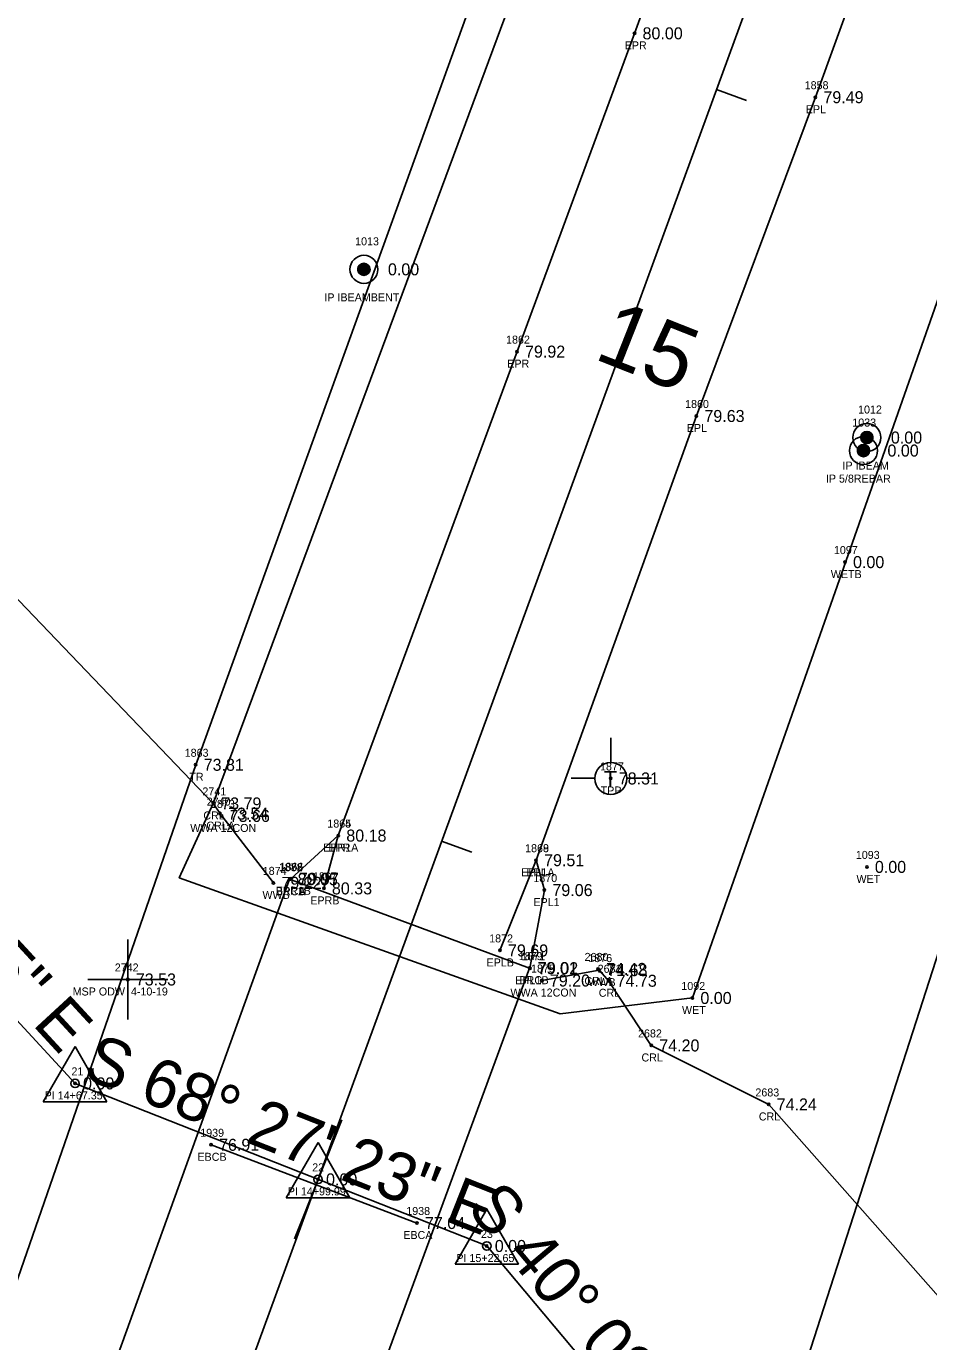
# Model space of a CAD drawing. Extents: x 2139392 to 2143384, y 505395 to 510520.
# Drawn here: x 2140668.2 to 2140780.9, y 508341.4 to 508505.7 of the extents above; entities that cross this region are included whole.
import ezdxf

# ---------------------------------------------------------------- set-up
doc = ezdxf.new("R2010")
doc.units = 0
for name, color, linetype in [('RD_EV_EX_Wetlands', 7, 'Continuous'), ('RD_EX_Bridge', 7, 'Continuous'), ('RD_EX_Bridge_txCode', 7, 'Continuous'), ('RD_EX_DV_Prop_txCode', 7, 'Continuous'), ('RD_EX_DV_PropPin', 7, 'Continuous'), ('RD_EX_H2O', 7, 'Continuous'), ('RD_EX_H2O_txCode', 7, 'Continuous'), ('RD_EX_H2O_WetLd_txCode', 7, 'Continuous'), ('RD_EX_Road', 7, 'Continuous'), ('RD_EX_Road_txCode', 7, 'Continuous'), ('RD_EX_TX_Bridge_ELEV', 7, 'Continuous'), ('RD_EX_TX_DV_Prop_ELEV', 7, 'Continuous'), ('RD_EX_TX_H2O_ELEV', 7, 'Continuous'), ('RD_EX_TX_H2O_WetLd_ELEV', 7, 'Continuous'), ('RD_EX_TX_Misc_ELEV', 7, 'Continuous'), ('RD_EX_TX_Road_ELEV', 7, 'Continuous'), ('RD_EX_TX_UT_ELEV', 7, 'Continuous'), ('RD_EX_TX_VEG_ELEV', 7, 'Continuous'), ('RD_EX_UT', 7, 'Continuous'), ('RD_EX_UT_txCode', 7, 'Continuous'), ('RD_EX_VEG', 7, 'Continuous'), ('RD_EX_VEG_txCode', 7, 'Continuous'), ('RD_HC_Cl', 7, 'Continuous'), ('RD_HC_Data', 7, 'Continuous'), ('RD_HC_Data_Tic', 7, 'Continuous'), ('RD_HC_Survey_ELEV', 7, 'Continuous'), ('RD_HC_TX_Sta50', 7, 'Continuous'), ('RD_HC_txCode', 7, 'Continuous'), ('RD_SMD_Locator', 7, 'Continuous')]:
    doc.layers.add(name, color=color, linetype=linetype)

msp = doc.modelspace()

# ---------------------------------------------------------------- linework, layer by layer
at = {"layer": 'RD_EV_EX_Wetlands'}
for p, q in [((2141031.31, 509324.16), (2140691.53, 508408.63)), ((2141075.3, 509306.14), (2140751.4, 508384.33)), ((2140734.86, 508382.37), (2140751.4, 508384.33))]:
    msp.add_line(p, q, dxfattribs=at)
msp.add_lwpolyline([(2140734.86, 508382.37), (2140687.28, 508399.34), (2140691.53, 508408.63)], dxfattribs=at)
at = {"layer": 'RD_EX_Bridge'}
for p, q in [((2140692.59, 508407.07), (2140699.06, 508398.71)), ((2140732.59, 508386.51), (2140739.77, 508387.81)), ((2140716.99, 508356.22), (2140691.26, 508365.99))]:
    msp.add_line(p, q, dxfattribs=at)
msp.add_lwpolyline([(2140701.08, 508399.16), (2140731.05, 508388.06), (2140707.41, 508323.76), (2140677.81, 508334.75), (2140701.08, 508399.16)], dxfattribs=at)
at = {"layer": 'RD_EX_DV_PropPin'}
for p, q in [((2140709.62, 508475.15), (2140709.62, 508475.54)), ((2140709.66, 508475.05), (2140709.66, 508475.64)), ((2140709.69, 508474.98), (2140709.69, 508475.71)), ((2140709.73, 508474.92), (2140709.73, 508475.77)), ((2140709.76, 508474.87), (2140709.76, 508475.82)), ((2140709.8, 508474.83), (2140709.8, 508475.86)), ((2140709.83, 508474.79), (2140709.83, 508475.9)), ((2140709.87, 508474.76), (2140709.87, 508475.93)), ((2140709.9, 508474.74), (2140709.9, 508475.95)), ((2140709.94, 508474.71), (2140709.94, 508475.98)), ((2140709.97, 508474.69), (2140709.97, 508476)), ((2140710.01, 508474.67), (2140710.01, 508476.02)), ((2140710.04, 508474.65), (2140710.04, 508476.04)), ((2140710.08, 508474.64), (2140710.08, 508476.05)), ((2140710.11, 508474.62), (2140710.11, 508476.07)), ((2140710.15, 508474.61), (2140710.15, 508476.08)), ((2140710.18, 508474.6), (2140710.18, 508476.09)), ((2140710.22, 508474.6), (2140710.22, 508476.09)), ((2140710.25, 508474.59), (2140710.25, 508476.1)), ((2140710.29, 508474.59), (2140710.29, 508476.1)), ((2140710.32, 508474.58), (2140710.32, 508476.11)), ((2140710.36, 508474.58), (2140710.36, 508476.11)), ((2140710.39, 508474.58), (2140710.39, 508476.11)), ((2140710.43, 508474.59), (2140710.43, 508476.1)), ((2140710.46, 508474.59), (2140710.46, 508476.1)), ((2140710.5, 508474.6), (2140710.5, 508476.09)), ((2140710.53, 508474.6), (2140710.53, 508476.09)), ((2140710.57, 508474.61), (2140710.57, 508476.08)), ((2140710.6, 508474.62), (2140710.6, 508476.07)), ((2140710.64, 508474.64), (2140710.64, 508476.05)), ((2140710.67, 508474.65), (2140710.67, 508476.04)), ((2140710.71, 508474.67), (2140710.71, 508476.02)), ((2140710.74, 508474.69), (2140710.74, 508476)), ((2140710.78, 508474.71), (2140710.78, 508475.98)), ((2140710.81, 508474.74), (2140710.81, 508475.95)), ((2140710.85, 508474.76), (2140710.85, 508475.93)), ((2140710.88, 508474.79), (2140710.88, 508475.9)), ((2140710.92, 508474.83), (2140710.92, 508475.86)), ((2140710.95, 508474.87), (2140710.95, 508475.82)), ((2140710.99, 508474.92), (2140710.99, 508475.77)), ((2140711.02, 508474.98), (2140711.02, 508475.71)), ((2140711.06, 508475.05), (2140711.06, 508475.64)), ((2140711.09, 508475.15), (2140711.09, 508475.54)), ((2140772.47, 508454.14), (2140772.47, 508454.53)), ((2140772.5, 508454.04), (2140772.5, 508454.64)), ((2140772.54, 508453.97), (2140772.54, 508454.71)), ((2140772.57, 508453.91), (2140772.57, 508454.76)), ((2140772.61, 508453.86), (2140772.61, 508454.81)), ((2140772.64, 508453.82), (2140772.64, 508454.85)), ((2140772.68, 508453.79), (2140772.68, 508454.89)), ((2140772.71, 508453.76), (2140772.71, 508454.92)), ((2140772.75, 508453.73), (2140772.75, 508454.95)), ((2140772.78, 508453.7), (2140772.78, 508454.97)), ((2140772.82, 508453.68), (2140772.82, 508454.99)), ((2140772.85, 508453.66), (2140772.85, 508455.01)), ((2140772.89, 508453.65), (2140772.89, 508455.03)), ((2140772.92, 508453.63), (2140772.92, 508455.05)), ((2140772.96, 508453.62), (2140772.96, 508455.06)), ((2140772.99, 508453.61), (2140772.99, 508455.07)), ((2140773.03, 508453.6), (2140773.03, 508455.08)), ((2140773.06, 508453.59), (2140773.06, 508455.09)), ((2140773.1, 508453.58), (2140773.1, 508455.09)), ((2140773.13, 508453.58), (2140773.13, 508455.1)), ((2140773.17, 508453.58), (2140773.17, 508455.1)), ((2140773.2, 508453.58), (2140773.2, 508455.1)), ((2140773.24, 508453.58), (2140773.24, 508455.1)), ((2140773.27, 508453.58), (2140773.27, 508455.1)), ((2140773.31, 508453.58), (2140773.31, 508455.09)), ((2140773.34, 508453.59), (2140773.34, 508455.09)), ((2140773.38, 508453.6), (2140773.38, 508455.08)), ((2140773.41, 508453.61), (2140773.41, 508455.07)), ((2140773.45, 508453.62), (2140773.45, 508455.06)), ((2140773.48, 508453.63), (2140773.48, 508455.05)), ((2140773.52, 508453.65), (2140773.52, 508455.03)), ((2140773.55, 508453.66), (2140773.55, 508455.01)), ((2140773.59, 508453.68), (2140773.59, 508454.99)), ((2140773.62, 508453.7), (2140773.62, 508454.97)), ((2140773.66, 508453.73), (2140773.66, 508454.95)), ((2140773.69, 508453.76), (2140773.69, 508454.92)), ((2140773.73, 508453.79), (2140773.73, 508454.89)), ((2140773.76, 508453.82), (2140773.76, 508454.85)), ((2140773.8, 508453.86), (2140773.8, 508454.81)), ((2140773.83, 508453.91), (2140773.83, 508454.76)), ((2140773.87, 508453.97), (2140773.87, 508454.71)), ((2140773.9, 508454.04), (2140773.9, 508454.64)), ((2140773.94, 508454.14), (2140773.94, 508454.53)), ((2140772.03, 508452.52), (2140772.03, 508452.91)), ((2140772.07, 508452.42), (2140772.07, 508453.01)), ((2140772.1, 508452.34), (2140772.1, 508453.08)), ((2140772.14, 508452.29), (2140772.14, 508453.14)), ((2140772.17, 508452.24), (2140772.17, 508453.19)), ((2140772.21, 508452.2), (2140772.21, 508453.23)), ((2140772.24, 508452.16), (2140772.24, 508453.27)), ((2140772.28, 508452.13), (2140772.28, 508453.3)), ((2140772.31, 508452.1), (2140772.31, 508453.32)), ((2140772.35, 508452.08), (2140772.35, 508453.35)), ((2140772.38, 508452.06), (2140772.38, 508453.37)), ((2140772.42, 508452.04), (2140772.42, 508453.39)), ((2140772.45, 508452.02), (2140772.45, 508453.41)), ((2140772.49, 508452.01), (2140772.49, 508453.42)), ((2140772.52, 508451.99), (2140772.52, 508453.43)), ((2140772.56, 508451.98), (2140772.56, 508453.45)), ((2140772.59, 508451.97), (2140772.59, 508453.45)), ((2140772.63, 508451.97), (2140772.63, 508453.46)), ((2140772.66, 508451.96), (2140772.66, 508453.47)), ((2140772.7, 508451.96), (2140772.7, 508453.47)), ((2140772.73, 508451.95), (2140772.73, 508453.47)), ((2140772.77, 508451.95), (2140772.77, 508453.48)), ((2140772.8, 508451.95), (2140772.8, 508453.47)), ((2140772.84, 508451.96), (2140772.84, 508453.47)), ((2140772.87, 508451.96), (2140772.87, 508453.47)), ((2140772.91, 508451.97), (2140772.91, 508453.46)), ((2140772.94, 508451.97), (2140772.94, 508453.45)), ((2140772.98, 508451.98), (2140772.98, 508453.45)), ((2140773.01, 508451.99), (2140773.01, 508453.43)), ((2140773.05, 508452.01), (2140773.05, 508453.42)), ((2140773.08, 508452.02), (2140773.08, 508453.41)), ((2140773.12, 508452.04), (2140773.12, 508453.39)), ((2140773.15, 508452.06), (2140773.15, 508453.37)), ((2140773.19, 508452.08), (2140773.19, 508453.35)), ((2140773.22, 508452.1), (2140773.22, 508453.32)), ((2140773.26, 508452.13), (2140773.26, 508453.3)), ((2140773.29, 508452.16), (2140773.29, 508453.27)), ((2140773.33, 508452.2), (2140773.33, 508453.23)), ((2140773.36, 508452.24), (2140773.36, 508453.19)), ((2140773.4, 508452.29), (2140773.4, 508453.14)), ((2140773.43, 508452.34), (2140773.43, 508453.08)), ((2140773.47, 508452.42), (2140773.47, 508453.01)), ((2140773.5, 508452.52), (2140773.5, 508452.91))]:
    msp.add_line(p, q, dxfattribs=at)
for centre, radius in [((2140710.36, 508475.35), 1.75), ((2140710.36, 508475.35), 0.761), ((2140773.2, 508454.34), 1.75), ((2140772.77, 508452.71), 1.75), ((2140773.2, 508454.34), 0.761), ((2140772.77, 508452.71), 0.761)]:
    msp.add_circle(centre, radius, dxfattribs=at)
at = {"layer": 'RD_EX_H2O'}
for p, q in [((2140680.86, 508381.64), (2140680.86, 508391.64)), ((2140675.86, 508386.64), (2140685.86, 508386.64))]:
    msp.add_line(p, q, dxfattribs=at)
for points in [[(2140692.39, 508407.36), (2140691.53, 508408.63), (2140655.07, 508446.65), (2140644.66, 508552.96), (2140647.23, 508625.31), (2140600.11, 508668.87)], [(2140739.62, 508387.96), (2140740.93, 508386.48), (2140746.26, 508378.4), (2140760.93, 508371.03), (2140783.4, 508345.61), (2140795.83, 508288.39), (2140821, 508236), (2140860.19, 508250.22), (2140881.65, 508244.68), (2140916.39, 508224.49), (2140943.62, 508213.42), (2140932.23, 508147.43), (2140918.3, 508109.01), (2140923.7, 508051.95), (2140980.19, 508013.39), (2141009.38, 508052.91), (2141114.83, 508040.99)]]:
    msp.add_lwpolyline(points, dxfattribs=at)
msp.add_circle((2140680.86, 508386.64), 0.15, dxfattribs=at)
at = {"layer": 'RD_EX_Road'}
msp.add_line((2140707.16, 508404.62), (2140701.22, 508399.22), dxfattribs=at)
for points in [[(2141086.27, 509371.27), (2141050.42, 509272.83), (2141015.08, 509176.39), (2140981.03, 509083.35), (2140979.15, 509077.9), (2140973.7, 509063.54), (2140966.53, 509043.25), (2140933.44, 508952.99), (2140896.92, 508852.59), (2140862.18, 508757.77), (2140824.9, 508656.32), (2140789.81, 508560.3), (2140766.77, 508496.85), (2140751.9, 508457.03), (2140731.87, 508401.54), (2140727.36, 508390.27)], [(2141052.52, 509348.48), (2141043.48, 509323.88), (2141027.84, 509280.54), (2140992.95, 509184.87), (2140958.53, 509091.45), (2140950.8, 509069.47), (2140944.28, 509052.06), (2140911.45, 508962.1), (2140874.65, 508861.6), (2140839.42, 508765.22), (2140802.38, 508664.56), (2140767.79, 508569.67), (2140744.17, 508504.83), (2140729.49, 508465.07), (2140707.16, 508404.62), (2140705.36, 508398.02)], [(2140731.87, 508401.54), (2140732.91, 508397.81), (2140731.11, 508388.05)]]:
    msp.add_lwpolyline(points, dxfattribs=at)
at = {"layer": 'RD_EX_UT'}
for p, q in [((2140741.2, 508416.82), (2140741.2, 508413.75)), ((2140736.27, 508411.77), (2140739.2, 508411.77)), ((2140743.2, 508411.77), (2140746.27, 508411.77))]:
    msp.add_line(p, q, dxfattribs=at)
msp.add_circle((2140741.2, 508411.75), 2, dxfattribs=at)
at = {"layer": 'RD_EX_VEG'}
for points in [[(2140900.08, 509397.36), (2141021.29, 509326.2), (2140852.61, 508865.26), (2140689.34, 508413.46), (2140624.53, 508226.48), (2140606.41, 508171.78), (2140591.23, 508116.67), (2140558.82, 507962.77), (2140538.78, 507709.07), (2140410.61, 507724.88)], [(2141197.74, 509262.45), (2141108.66, 509301.7), (2140947.3, 508831.92), (2140798.26, 508440.01), (2140718.9, 508193.9), (2140671.92, 508048.02), (2140772.34, 507989.74)]]:
    msp.add_lwpolyline(points, dxfattribs=at)
at = {"layer": 'RD_HC_Cl'}
for p, q in [((2141333.53, 510081.69), (2140670.51, 508268.37)), ((2140632.92, 508418.51), (2140674.27, 508373.66)), ((2140674.27, 508373.66), (2140725.71, 508353.35)), ((2140725.71, 508353.35), (2140753.91, 508319.8))]:
    msp.add_line(p, q, dxfattribs=at)
at = {"layer": 'RD_HC_Data'}
for p, q in [((2140670.3, 508371.37), (2140674.27, 508378.25)), ((2140674.27, 508378.25), (2140678.24, 508371.37)), ((2140670.3, 508371.37), (2140678.24, 508371.37)), ((2140700.66, 508359.38), (2140704.63, 508366.26)), ((2140704.63, 508366.26), (2140708.6, 508359.38)), ((2140700.66, 508359.38), (2140708.6, 508359.38)), ((2140721.74, 508351.06), (2140725.71, 508357.94)), ((2140725.71, 508357.94), (2140729.68, 508351.06)), ((2140721.74, 508351.06), (2140729.68, 508351.06))]:
    msp.add_line(p, q, dxfattribs=at)
for centre in [(2140674.27, 508373.66), (2140704.63, 508361.67), (2140725.71, 508353.35)]:
    msp.add_circle(centre, 0.529, dxfattribs=at)
at = {"layer": 'RD_HC_Data_Tic'}
for p, q in [((2140754.41, 508497.83), (2140758.17, 508496.45)), ((2140720.07, 508403.91), (2140723.83, 508402.54)), ((2140704.64, 508361.67), (2140707.58, 508369.11)), ((2140704.64, 508361.67), (2140701.7, 508354.23))]:
    msp.add_line(p, q, dxfattribs=at)
at = {"layer": 'RD_SMD_Locator'}
for centre in [(2140744.17, 508504.83), (2140766.77, 508496.85), (2140710.36, 508475.35), (2140729.49, 508465.07), (2140751.9, 508457.03), (2140773.2, 508454.34), (2140772.77, 508452.71), (2140770.47, 508438.78), (2140689.34, 508413.46), (2140741.2, 508411.75), (2140691.53, 508408.63), (2140692.39, 508407.36), (2140692.59, 508407.07), (2140707.16, 508404.62), (2140707.16, 508404.62), (2140731.87, 508401.54), (2140731.87, 508401.54), (2140773.2, 508400.7), (2140699.06, 508398.71), (2140701.08, 508399.16), (2140701.08, 508399.16), (2140701.22, 508399.22), (2140705.36, 508398.02), (2140732.91, 508397.81), (2140727.36, 508390.27), (2140731.05, 508388.06), (2140731.11, 508388.05), (2140732.59, 508386.51), (2140739.62, 508387.96), (2140739.77, 508387.81), (2140740.93, 508386.48), (2140751.4, 508384.33), (2140746.26, 508378.4), (2140674.27, 508373.66), (2140760.93, 508371.03), (2140691.26, 508365.99), (2140704.63, 508361.67), (2140716.99, 508356.22), (2140725.71, 508353.35)]:
    msp.add_circle(centre, 0.15, dxfattribs=at)

# ---------------------------------------------------------------- texts
at = {"layer": 'RD_EX_Bridge_txCode'}
for s, p in [('1873', (2140691.25, 508408.07)), ('WWA 12CON', (2140688.66, 508405.07)), ('1874', (2140697.72, 508399.71)), ('1878', (2140699.73, 508400.16)), ('1882', (2140699.73, 508400.16)), ('BRCA', (2140699.34, 508397.16)), ('BRCB', (2140699.36, 508397.16)), ('WWB', (2140697.68, 508396.71)), ('1879', (2140729.7, 508389.06)), ('1875', (2140731.24, 508387.51)), ('1876', (2140738.4, 508388.81)), ('BRC', (2140729.79, 508386.06)), ('WWB', (2140738.39, 508385.81)), ('WWA 12CON', (2140728.66, 508384.51)), ('1939', (2140689.91, 508366.99)), ('EBCB', (2140689.56, 508363.99)), ('1938', (2140715.65, 508357.22)), ('EBCA', (2140715.28, 508354.22))]:
    msp.add_text(s, height=1, dxfattribs=at).set_placement(p)
at = {"layer": 'RD_EX_DV_Prop_txCode'}
for s, p in [('1013', (2140709.26, 508478.35)), ('IP IBEAMBENT', (2140705.42, 508471.35)), ('1012', (2140772.1, 508457.34)), ('1033', (2140771.38, 508455.71)), ('IP IBEAM', (2140770.15, 508450.34)), ('IP 5/8REBAR', (2140768.08, 508448.71))]:
    msp.add_text(s, height=1, dxfattribs=at).set_placement(p)
at = {"layer": 'RD_EX_H2O_txCode'}
for s, p in [('2741', (2140690.18, 508409.63)), ('2740', (2140690.72, 508408.36)), ('CRL', (2140690.3, 508406.63)), ('CRLA', (2140690.67, 508405.36)), ('2680', (2140737.93, 508388.96)), ('2742', (2140679.23, 508387.64)), ('2681', (2140739.56, 508387.48)), ('CRLA', (2140737.91, 508385.96)), ('MSP ODW  4-10-19', (2140673.97, 508384.64)), ('CRL', (2140739.7, 508384.48)), ('2682', (2140744.61, 508379.4)), ('CRL', (2140745.04, 508376.4)), ('2683', (2140759.27, 508372.03)), ('CRL', (2140759.7, 508369.03))]:
    msp.add_text(s, height=1, dxfattribs=at).set_placement(p)
at = {"layer": 'RD_EX_H2O_WetLd_txCode'}
for s, p in [('1097', (2140769.08, 508439.78)), ('WETB', (2140768.69, 508436.78)), ('1093', (2140771.82, 508401.7)), ('WET', (2140771.9, 508398.7)), ('1092', (2140750.02, 508385.33)), ('WET', (2140750.1, 508382.33))]:
    msp.add_text(s, height=1, dxfattribs=at).set_placement(p)
at = {"layer": 'RD_EX_Road_txCode'}
for s, p in [('EPR', (2140742.94, 508502.83)), ('1858', (2140765.43, 508497.85)), ('EPL', (2140765.57, 508494.85)), ('1862', (2140728.12, 508466.07)), ('EPR', (2140728.27, 508463.07)), ('1860', (2140750.49, 508458.03)), ('EPL', (2140750.7, 508455.03)), ('1864', (2140705.79, 508405.62)), ('1865', (2140705.79, 508405.62)), ('EPR1A', (2140705.27, 508402.62)), ('EPR', (2140705.93, 508402.62)), ('1868', (2140730.5, 508402.54)), ('1869', (2140730.5, 508402.54)), ('1866', (2140699.82, 508400.22)), ('1867', (2140703.99, 508399.02)), ('EPL1A', (2140730.01, 508399.54)), ('EPL', (2140730.67, 508399.54)), ('1870', (2140731.53, 508398.81)), ('EPR1B', (2140699.35, 508397.22)), ('EPRB', (2140703.66, 508396.02)), ('EPL1', (2140731.54, 508395.81)), ('1872', (2140726.01, 508391.27)), ('1871', (2140730.05, 508389.05)), ('EPLB', (2140725.68, 508388.27)), ('EPL1B', (2140729.27, 508386.05))]:
    msp.add_text(s, height=1, dxfattribs=at).set_placement(p)
at = {"layer": 'RD_EX_TX_Bridge_ELEV'}
for s, p in [('73.66', (2140693.59, 508406.32)), ('80.05', (2140702.08, 508398.41)), ('80.05', (2140702.08, 508398.41)), ('79.22', (2140700.06, 508397.96)), ('79.01', (2140732.05, 508387.31)), ('74.68', (2140740.77, 508387.06)), ('79.20', (2140733.59, 508385.76)), ('76.91', (2140692.26, 508365.24)), ('77.04', (2140717.99, 508355.47))]:
    msp.add_text(s, height=1.5, dxfattribs=at).set_placement(p)
at = {"layer": 'RD_EX_TX_DV_Prop_ELEV'}
for p in [(2140713.36, 508474.6), (2140776.2, 508453.59), (2140775.77, 508451.96)]:
    msp.add_text('0.00', height=1.5, dxfattribs=at).set_placement(p)
at = {"layer": 'RD_EX_TX_H2O_ELEV'}
for s, p in [('73.79', (2140692.53, 508407.88)), ('73.54', (2140693.39, 508406.61)), ('74.42', (2140740.62, 508387.21)), ('74.73', (2140741.93, 508385.73)), ('74.20', (2140747.26, 508377.65)), ('74.24', (2140761.93, 508370.28))]:
    msp.add_text(s, height=1.5, dxfattribs=at).set_placement(p)
at = {"layer": 'RD_EX_TX_H2O_WetLd_ELEV'}
for p in [(2140771.47, 508438.03), (2140774.2, 508399.95), (2140752.4, 508383.58)]:
    msp.add_text('0.00', height=1.5, dxfattribs=at).set_placement(p)
at = {"layer": 'RD_EX_TX_Misc_ELEV'}
msp.add_text('73.53', height=1.5, dxfattribs=at).set_placement((2140681.86, 508385.89))
at = {"layer": 'RD_EX_TX_Road_ELEV'}
for s, p in [('80.00', (2140745.17, 508504.08)), ('79.49', (2140767.77, 508496.1)), ('79.92', (2140730.49, 508464.32)), ('79.63', (2140752.9, 508456.28)), ('80.18', (2140708.16, 508403.87)), ('80.18', (2140708.16, 508403.87)), ('79.51', (2140732.87, 508400.79)), ('79.51', (2140732.87, 508400.79)), ('79.97', (2140702.22, 508398.47)), ('80.33', (2140706.36, 508397.27)), ('79.06', (2140733.91, 508397.06)), ('79.69', (2140728.36, 508389.52)), ('79.02', (2140732.11, 508387.3))]:
    msp.add_text(s, height=1.5, dxfattribs=at).set_placement(p)
at = {"layer": 'RD_EX_TX_UT_ELEV'}
msp.add_text('78.31', height=1.5, dxfattribs=at).set_placement((2140742.2, 508411))
at = {"layer": 'RD_EX_TX_VEG_ELEV'}
msp.add_text('73.81', height=1.5, dxfattribs=at).set_placement((2140690.34, 508412.71))
at = {"layer": 'RD_EX_UT'}
msp.add_text('T', height=2, dxfattribs=at).set_placement((2140740.35, 508410.7))
at = {"layer": 'RD_EX_UT_txCode'}
for s, p in [('1877', (2140739.86, 508412.75)), ('TPP', (2140739.94, 508409.75))]:
    msp.add_text(s, height=1, dxfattribs=at).set_placement(p)
at = {"layer": 'RD_EX_VEG_txCode'}
for s, p in [('1863', (2140687.97, 508414.46)), ('TR', (2140688.55, 508411.46))]:
    msp.add_text(s, height=1, dxfattribs=at).set_placement(p)
at = {"layer": 'RD_HC_Data'}
for s, rotation, p in [('S 42%%d 40\' 25" E', 312.6737, (2140635.87, 508416.79)), ('S 68%%d 27\' 23" E', 338.4564, (2140675.02, 508374.44)), ('S 40%%d 03\' 01" E', 310.0502, (2140723.05, 508358.08))]:
    msp.add_text(s, height=6, rotation=rotation, dxfattribs=at).set_placement(p)
at = {"layer": 'RD_HC_Survey_ELEV'}
for p in [(2140675.27, 508372.91), (2140705.63, 508360.92), (2140726.71, 508352.6)]:
    msp.add_text('0.00', height=1.5, dxfattribs=at).set_placement(p)
at = {"layer": 'RD_HC_TX_Sta50'}
msp.add_text('15', height=8, rotation=338.4564, dxfattribs=at).set_placement((2140738.94, 508464.24))
at = {"layer": 'RD_HC_txCode'}
for s, p in [('21', (2140673.82, 508374.66)), ('PI 14+67.35', (2140670.47, 508371.66)), ('22', (2140703.9, 508362.67)), ('PI 14+99.99', (2140700.85, 508359.67)), ('23', (2140724.98, 508354.35)), ('PI 15+22.65', (2140721.91, 508351.35))]:
    msp.add_text(s, height=1, dxfattribs=at).set_placement(p)

doc.saveas('drawing.dxf')
